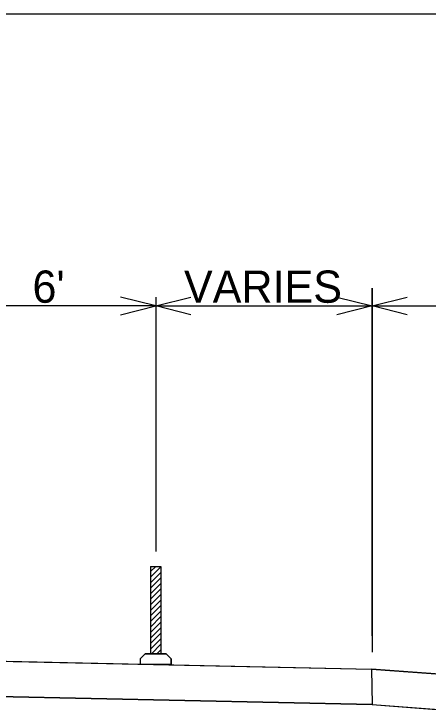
# Model space of a CAD drawing. Extents: x 10133 to 81668, y 4856 to 11018.
# Drawn here: x 11731.9 to 11924.8, y 9622.2 to 9944 of the extents above; entities that cross this region are included whole.
import ezdxf

# ---------------------------------------------------------------- set-up
doc = ezdxf.new("R2010")
doc.units = 0
for name, color, linetype in [('dsnStdBorder', 7, 'Continuous'), ('dsnXsPCCPavementBottom', 7, 'Continuous'), ('dsnXsShldrEarthFill', 7, 'Continuous'), ('dsnXsShldrGranular', 7, 'Continuous'), ('dsnXsShldrGranularBottom', 7, 'Continuous'), ('dsnXsShldrSpecialBackBottom', 7, 'Continuous'), ('SheetBorder', 7, 'Continuous')]:
    doc.layers.add(name, color=color, linetype=linetype)

msp = doc.modelspace()

# ---------------------------------------------------------------- linework, layer by layer
at = {"layer": 'dsnStdBorder'}
for p, q in [((11795.52, 9686.79), (11800.34, 9686.79)), ((11795.52, 9686.79), (11795.52, 9646.13)), ((11795.52, 9684.37), (11797.94, 9686.79)), ((11800.34, 9686.79), (11800.34, 9646.13)), ((11795.52, 9681.79), (11800.34, 9686.61)), ((11795.52, 9679.21), (11800.34, 9684.03)), ((11795.52, 9676.64), (11800.34, 9681.46)), ((11795.52, 9674.06), (11800.34, 9678.88)), ((11795.52, 9671.48), (11800.34, 9676.3)), ((11795.52, 9668.9), (11800.34, 9673.72)), ((11795.52, 9666.33), (11800.34, 9671.15)), ((11795.52, 9663.75), (11800.34, 9668.57)), ((11795.52, 9661.17), (11800.34, 9665.99)), ((11795.52, 9658.59), (11800.34, 9663.41)), ((11795.52, 9656.02), (11800.34, 9660.84)), ((11795.52, 9653.44), (11800.34, 9658.26)), ((11795.52, 9650.86), (11800.34, 9655.68)), ((11795.52, 9648.29), (11800.34, 9653.11)), ((11795.95, 9646.13), (11800.34, 9650.53)), ((11793.11, 9646.13), (11790.7, 9643.74)), ((11793.11, 9646.13), (11790.7, 9643.74)), ((11795.52, 9646.13), (11793.11, 9646.13)), ((11793.11, 9646.13), (11802.75, 9646.13)), ((11800.34, 9646.13), (11795.52, 9646.13)), ((11798.53, 9646.13), (11800.34, 9647.95)), ((11802.75, 9646.13), (11800.34, 9646.13)), ((11805.16, 9643.74), (11802.75, 9646.13)), ((11802.75, 9646.13), (11805.16, 9643.74)), ((11790.7, 9643.74), (11790.7, 9641.35)), ((11790.7, 9643.74), (11790.7, 9641.35)), ((11805.16, 9641.35), (11805.16, 9643.74)), ((11805.16, 9643.74), (11805.16, 9641.35)), ((11790.7, 9641.35), (11805.16, 9641.35)), ((11790.7, 9641.35), (11805.16, 9641.35))]:
    msp.add_line(p, q, dxfattribs=at)
at = {"layer": 'dsnXsPCCPavementBottom'}
for p, q in [((11898.67, 9654.52), (11898.67, 9816.39)), ((11898.67, 9816.39), (11898.67, 9654.52)), ((11898.67, 9816.39), (11898.67, 9646.85)), ((11797.93, 9812.17), (11797.93, 9693.71)), ((11797.93, 9808.07), (11699.76, 9808.07)), ((11797.93, 9808.07), (11898.67, 9808.07)), ((11898.67, 9808.07), (11996.08, 9808.07))]:
    msp.add_line(p, q, dxfattribs=at)
for points in [[(11781.54, 9803.97), (11797.93, 9808.07), (11781.54, 9812.17)], [(11814.32, 9803.97), (11797.93, 9808.07), (11814.32, 9812.17)], [(11882.28, 9812.17), (11898.67, 9808.07), (11882.28, 9803.97)], [(11915.06, 9803.97), (11898.67, 9808.07), (11915.06, 9812.17)]]:
    msp.add_lwpolyline(points, dxfattribs=at)
at = {"layer": 'dsnXsShldrGranular'}
msp.add_line((11898.67, 9622.47), (11699.65, 9626.7), dxfattribs=at)
msp.add_lwpolyline([(11700, 9643.25), (11898.43, 9639.03), (11898.67, 9622.47)], dxfattribs=at)
msp.add_lwpolyline([(11996.08, 9631.76), (11898.43, 9639.03), (11898.67, 9622.47), (11996.08, 9615.16)], close=True, dxfattribs=at)
at = {"layer": 'dsnXsShldrGranularBottom'}
for p, q in [((11700, 9643.25), (11898.43, 9639.03)), ((11898.43, 9639.03), (11898.67, 9622.47)), ((11898.43, 9639.03), (11898.67, 9622.47)), ((11898.43, 9639.03), (11898.67, 9622.47)), ((11898.43, 9639.03), (11898.67, 9622.47)), ((11699.65, 9626.7), (11898.67, 9622.47))]:
    msp.add_line(p, q, dxfattribs=at)
at = {"layer": 'dsnXsShldrSpecialBackBottom'}
for p, q in [((11898.43, 9639.03), (11996.08, 9631.76)), ((11898.67, 9622.47), (11996.08, 9615.16))]:
    msp.add_line(p, q, dxfattribs=at)
at = {"layer": 'SheetBorder'}
msp.add_lwpolyline([(10132.52, 9944.02), (13267.53, 9944.02), (13267.53, 7924.02), (10132.52, 7924.02)], close=True, dxfattribs=at)

# ---------------------------------------------------------------- texts
at = {"layer": 'dsnXsShldrEarthFill'}
for s, p in [("6'", (11740.57, 9809.53)), ('VARIES', (11811.1, 9809.53))]:
    msp.add_text(s, height=15, dxfattribs=at).set_placement(p)

doc.saveas('drawing.dxf')
